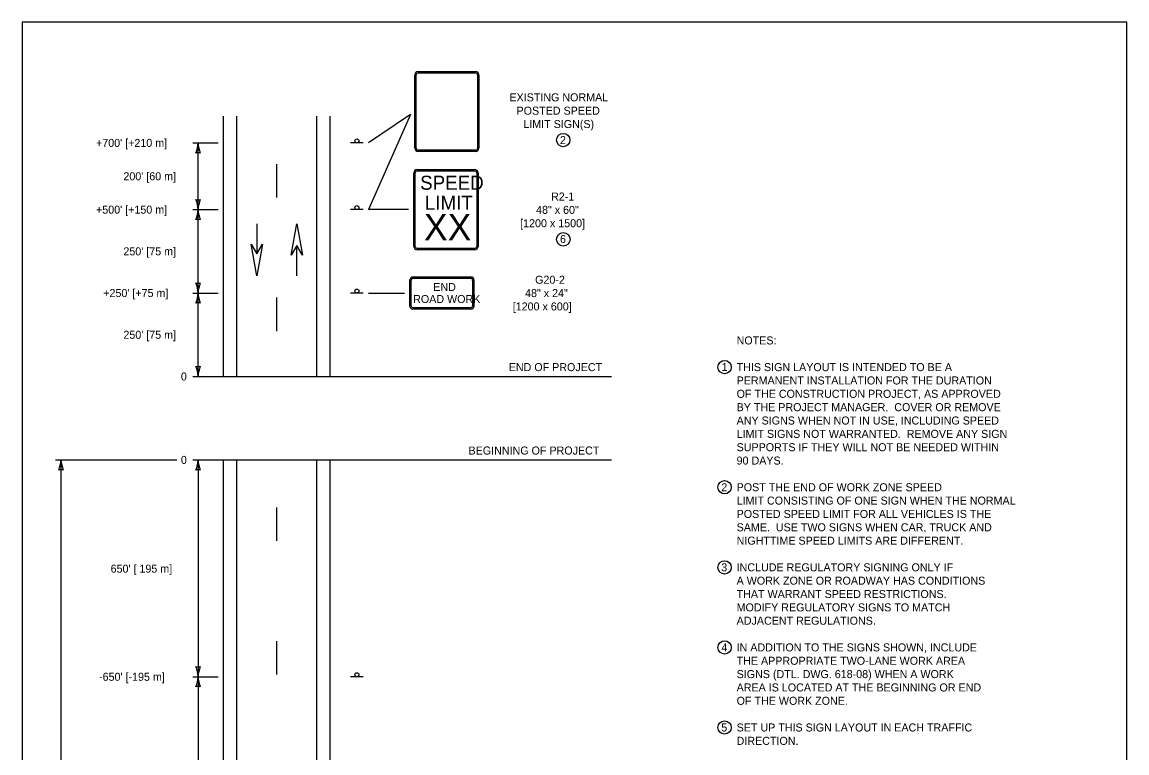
# Model space of a CAD drawing. Extents: x 49991.4 to 50021, y 49987.6 to 50011.4.
# Drawn here: x 50000.34 to 50008.61, y 50005.79 to 50011.26 of the extents above; entities that cross this region are included whole.
import ezdxf

# ---------------------------------------------------------------- set-up
doc = ezdxf.new("R2010")
doc.units = 0
for name, color, linetype in [('Level 1', 7, 'Continuous'), ('Level 2', 7, 'Continuous'), ('Level 3', 7, 'Continuous')]:
    doc.layers.add(name, color=color, linetype=linetype)

msp = doc.modelspace()

# ---------------------------------------------------------------- linework, layer by layer
at = {"layer": 'Level 1'}
for p, q in [((50003.3039, 50010.8925), (50003.7339, 50010.8925)), ((50003.3039, 50010.8825), (50003.7339, 50010.8825)), ((50003.2789, 50010.3175), (50003.2789, 50010.8675)), ((50003.2889, 50010.3175), (50003.2889, 50010.8675)), ((50003.7489, 50010.8675), (50003.7489, 50010.3175)), ((50003.7589, 50010.8675), (50003.7589, 50010.3175)), ((50001.8443, 50008.6077), (50001.8443, 50010.5577)), ((50001.8443, 50008.6077), (50001.8443, 50010.5577)), ((50001.9443, 50008.6077), (50001.9443, 50010.5577)), ((50001.9443, 50008.6077), (50001.9443, 50010.5577)), ((50002.5443, 50008.6077), (50002.5443, 50010.5577)), ((50002.5443, 50008.6077), (50002.5443, 50010.5577)), ((50002.6443, 50008.6077), (50002.6443, 50010.5577)), ((50002.6443, 50008.6077), (50002.6443, 50010.5577)), ((50002.8923, 50010.3577), (50002.7963, 50010.3577)), ((50002.8923, 50010.3577), (50002.7963, 50010.3577)), ((50003.7339, 50010.3025), (50003.3039, 50010.3025)), ((50003.7339, 50010.2925), (50003.3039, 50010.2925)), ((50002.2443, 50009.9482), (50002.2443, 50010.1982)), ((50002.2443, 50009.9482), (50002.2443, 50010.1982)), ((50003.272, 50009.5825), (50003.272, 50010.1325)), ((50003.282, 50009.5825), (50003.282, 50010.1325)), ((50003.297, 50010.1575), (50003.727, 50010.1575)), ((50003.297, 50010.1475), (50003.727, 50010.1475)), ((50003.742, 50010.1325), (50003.742, 50009.5825)), ((50003.752, 50010.1325), (50003.752, 50009.5825)), ((50002.8923, 50009.8575), (50002.7963, 50009.8575)), ((50002.8923, 50009.8575), (50002.7963, 50009.8575)), ((50002.094, 50009.7524), (50002.094, 50009.5265)), ((50002.094, 50009.7524), (50002.094, 50009.5265)), ((50002.0943, 50009.7524), (50002.0943, 50009.5265)), ((50002.0943, 50009.7524), (50002.0943, 50009.5265)), ((50002.394, 50009.3623), (50002.394, 50009.5882)), ((50002.394, 50009.3623), (50002.394, 50009.5882)), ((50002.3943, 50009.3623), (50002.3943, 50009.5882)), ((50002.3943, 50009.3623), (50002.3943, 50009.5882)), ((50003.727, 50009.5675), (50003.297, 50009.5675)), ((50003.727, 50009.5575), (50003.297, 50009.5575)), ((50003.2419, 50009.1325), (50003.2419, 50009.3325)), ((50003.2519, 50009.1375), (50003.2519, 50009.3275)), ((50003.7019, 50009.3525), (50003.2619, 50009.3525)), ((50003.6969, 50009.3425), (50003.2669, 50009.3425)), ((50003.7119, 50009.3275), (50003.7119, 50009.1375)), ((50003.7219, 50009.3325), (50003.7219, 50009.1325)), ((50002.8923, 50009.2325), (50002.7963, 50009.2325)), ((50002.8923, 50009.2325), (50002.7963, 50009.2325)), ((50002.2443, 50008.9482), (50002.2443, 50009.1982)), ((50002.2443, 50008.9482), (50002.2443, 50009.1982)), ((50003.7018, 50009.1125), (50003.2618, 50009.1125)), ((50003.6969, 50009.1225), (50003.2669, 50009.1225)), ((50001.8443, 50002.7972), (50001.8443, 50007.9828)), ((50001.8443, 50002.7972), (50001.8443, 50007.9828)), ((50001.9443, 50002.7972), (50001.9443, 50007.9828)), ((50001.9443, 50002.7972), (50001.9443, 50007.9828)), ((50002.5443, 50002.7972), (50002.5443, 50007.9828)), ((50002.5443, 50002.7972), (50002.5443, 50007.9828)), ((50002.6443, 50002.7972), (50002.6443, 50007.9828)), ((50002.6443, 50002.7972), (50002.6443, 50007.9828)), ((50002.2443, 50007.3756), (50002.2443, 50007.6256)), ((50002.2443, 50007.3756), (50002.2443, 50007.6256)), ((50002.2443, 50006.3756), (50002.2443, 50006.6256)), ((50002.2443, 50006.3756), (50002.2443, 50006.6256)), ((50002.8923, 50006.3575), (50002.7963, 50006.3575)), ((50002.8923, 50006.3575), (50002.7963, 50006.3575))]:
    msp.add_line(p, q, dxfattribs=at)
for points in [[(50008.6146, 50011.2628), (50000.3356, 50011.2628), (50000.3356, 50000.0624), (50008.6146, 50000.0624)], [(50002.3523, 50009.5159), (50002.394, 50009.7524), (50002.4359, 50009.5159), (50002.394, 50009.5881)], [(50002.3523, 50009.5159), (50002.394, 50009.7524), (50002.4359, 50009.5159), (50002.394, 50009.5881)], [(50002.136, 50009.5988), (50002.0943, 50009.3623), (50002.0524, 50009.5988), (50002.0943, 50009.5266)], [(50002.136, 50009.5988), (50002.0943, 50009.3623), (50002.0524, 50009.5988), (50002.0943, 50009.5266)]]:
    msp.add_lwpolyline(points, close=True, dxfattribs=at)
for centre in [(50002.8443, 50010.3728), (50002.8443, 50010.3728), (50002.8443, 50009.8728), (50002.8443, 50009.8728), (50002.8443, 50009.2478), (50002.8443, 50009.2478), (50002.8443, 50006.3728), (50002.8443, 50006.3728)]:
    msp.add_circle(centre, 0.0152, dxfattribs=at)
for centre, radius, start, end in [((50003.3039, 50010.8676), 0.025, 90, 180), ((50003.3039, 50010.8676), 0.015, 90, 180), ((50003.7339, 50010.8676), 0.025, 0, 90), ((50003.7339, 50010.8676), 0.015, 0, 90), ((50003.3039, 50010.3176), 0.025, 180, 270), ((50003.3039, 50010.3176), 0.015, 180, 270), ((50003.7339, 50010.3176), 0.025, 270, 0), ((50003.7339, 50010.3176), 0.015, 270, 0), ((50003.297, 50010.1326), 0.025, 90, 180), ((50003.297, 50010.1326), 0.015, 90, 180), ((50003.727, 50010.1326), 0.025, 0, 90), ((50003.727, 50010.1326), 0.015, 0, 90), ((50003.297, 50009.5826), 0.025, 180, 270), ((50003.297, 50009.5826), 0.015, 180, 270), ((50003.727, 50009.5826), 0.025, 270, 0), ((50003.727, 50009.5826), 0.015, 270, 0), ((50003.2619, 50009.3325), 0.02, 90, 180), ((50003.2669, 50009.3275), 0.015, 90, 180), ((50003.6969, 50009.3275), 0.015, 360, 90), ((50003.7019, 50009.3325), 0.02, 360, 90), ((50003.2669, 50009.1375), 0.015, 180, 270), ((50003.6969, 50009.1375), 0.015, 270, 360), ((50003.2618, 50009.1325), 0.02, 180, 270), ((50003.7018, 50009.1325), 0.02, 270, 360)]:
    msp.add_arc(centre, radius, start, end, dxfattribs=at)
at = {"layer": 'Level 2'}
for centre, radius in [((50004.391, 50010.3791), 0.05), ((50004.3908, 50009.6352), 0.0507), ((50005.6, 50008.6777), 0.05), ((50005.6, 50007.7776), 0.05), ((50005.6, 50007.7776), 0.05), ((50005.6, 50007.1776), 0.05), ((50005.6, 50007.1776), 0.05), ((50005.6, 50006.5777), 0.05), ((50005.5998, 50005.9777), 0.05)]:
    msp.add_circle(centre, radius, dxfattribs=at)
at = {"layer": 'Level 3'}
for p, q in [((50003.2458, 50010.5701), (50002.9323, 50010.3577)), ((50003.2458, 50010.5701), (50002.9323, 50009.8575)), ((50001.6143, 50010.3577), (50001.8043, 50010.3577)), ((50001.6543, 50009.8578), (50001.6543, 50010.3577)), ((50001.6143, 50009.8577), (50001.8043, 50009.8577)), ((50001.6543, 50009.2327), (50001.6543, 50009.8577)), ((50003.232, 50009.8575), (50002.9323, 50009.8575)), ((50001.6143, 50009.2327), (50001.8043, 50009.2327)), ((50001.6543, 50008.6077), (50001.6543, 50009.2327)), ((50002.9323, 50009.2325), (50003.2019, 50009.2325)), ((50001.6143, 50008.6077), (50004.7528, 50008.6077)), ((50000.587, 50007.9828), (50001.4944, 50007.9828)), ((50000.627, 50007.9828), (50000.627, 50002.0173)), ((50001.6143, 50007.9827), (50002.7563, 50007.9827)), ((50001.6543, 50007.9827), (50001.6543, 50006.7896)), ((50002.7563, 50007.9828), (50004.7528, 50007.9828)), ((50002.7563, 50007.9828), (50004.7528, 50007.9828)), ((50001.6543, 50006.7896), (50001.6543, 50006.3577)), ((50001.6143, 50006.3577), (50001.8043, 50006.3577)), ((50001.6543, 50006.3577), (50001.6543, 50004.8576))]:
    msp.add_line(p, q, dxfattribs=at)
for centre, radius, start, end in [((50001.4322, 50010.3669), 0.2223, 337.45601, 357.63952), ((50001.887, 50010.3692), 0.233, 182.82731, 202.07716), ((50001.6543, 50010.2295), 0.0548, 72.13882, 107.86118), ((50001.6543, 50009.986), 0.0548, 252.13882, 287.86118), ((50001.4216, 50009.8463), 0.233, 2.82731, 22.07716), ((50001.8764, 50009.8486), 0.2223, 157.45601, 177.63952), ((50001.4322, 50009.8669), 0.2223, 337.45601, 357.63952), ((50001.887, 50009.8692), 0.233, 182.82731, 202.07716), ((50001.6543, 50009.7295), 0.0548, 72.13882, 107.86118), ((50001.6543, 50009.3609), 0.0548, 252.13882, 287.86118), ((50001.4216, 50009.2212), 0.233, 2.82731, 22.07716), ((50001.8764, 50009.2236), 0.2223, 157.45601, 177.63952), ((50001.4322, 50009.2419), 0.2223, 337.45601, 357.63952), ((50001.887, 50009.2442), 0.233, 182.82731, 202.07716), ((50001.6543, 50009.1045), 0.0548, 72.13882, 107.86118), ((50001.6543, 50008.7359), 0.0548, 252.13882, 287.86118), ((50001.4216, 50008.5962), 0.233, 2.82731, 22.07716), ((50001.8764, 50008.5986), 0.2223, 157.45601, 177.63952), ((50000.4049, 50007.9919), 0.2223, 337.45601, 357.63952), ((50000.8597, 50007.9942), 0.233, 182.82731, 202.07716), ((50001.4322, 50007.9919), 0.2223, 337.45601, 357.63952), ((50001.887, 50007.9942), 0.233, 182.82731, 202.07716), ((50000.627, 50007.8545), 0.0548, 72.13882, 107.86118), ((50001.6543, 50007.8545), 0.0548, 72.13882, 107.86118), ((50001.6543, 50006.4859), 0.0548, 252.13882, 287.86118), ((50001.4216, 50006.3462), 0.233, 2.82731, 22.07716), ((50001.8764, 50006.3486), 0.2223, 157.45601, 177.63952), ((50001.4322, 50006.3669), 0.2223, 337.45601, 357.63952), ((50001.887, 50006.3692), 0.233, 182.82731, 202.07716), ((50001.6543, 50006.2295), 0.0548, 72.13882, 107.86118)]:
    msp.add_arc(centre, radius, start, end, dxfattribs=at)

# ---------------------------------------------------------------- texts
at = {"layer": 'Level 1'}
for s, height, p in [('SPEED', 0.10512, (50003.3183, 50010.0067)), ('LIMIT', 0.10512, (50003.3537, 50009.8566)), ('XX', 0.19892, (50003.3471, 50009.6271))]:
    msp.add_text(s, height=height, dxfattribs=at).set_placement(p)
for s, p in [('END', (50003.4167, 50009.2479)), ('ROAD WORK', (50003.266, 50009.1579))]:
    msp.add_text(s, height=0.06, rotation=360, dxfattribs=at).set_placement(p)
at = {"layer": 'Level 2'}
for s, p in [('EXISTING NORMAL', (50003.9873, 50010.6691)), ('POSTED SPEED', (50004.0408, 50010.5691)), ('LIMIT SIGN(S)', (50004.0916, 50010.4691)), ("+700' [+210 m]", (50000.8897, 50010.3277)), ('2', (50004.3659, 50010.3491)), ("200' [60 m]", (50001.0948, 50010.0777)), ('R2-1', (50004.2994, 50009.9259)), ("+500' [+150 m]", (50000.8897, 50009.8277)), ('48" x 60"', (50004.1871, 50009.8259)), ('[1200 x 1500]', (50004.0677, 50009.7259)), ('6', (50004.3663, 50009.6073)), ("250' [75 m]", (50001.0948, 50009.5152)), ('G20-2', (50004.18, 50009.3025)), ("+250' [+75 m]", (50000.9436, 50009.2027)), ('48" x 24"', (50004.1048, 50009.2025)), ('[1200 x 600]', (50004.0123, 50009.1025)), ("250' [75 m]", (50001.0948, 50008.8902)), ('NOTES:', (50005.69, 50008.8477)), ('0', (50001.5257, 50008.5777)), ('END OF PROJECT', (50003.9823, 50008.6477)), ('1', (50005.5773, 50008.649)), ('THIS SIGN LAYOUT IS INTENDED TO BE A', (50005.69, 50008.6477)), ('PERMANENT INSTALLATION FOR THE DURATION', (50005.69, 50008.5477)), ('OF THE CONSTRUCTION PROJECT, AS APPROVED', (50005.69, 50008.4477)), ('BY THE PROJECT MANAGER.  COVER OR REMOVE', (50005.69, 50008.3477)), ('ANY SIGNS WHEN NOT IN USE, INCLUDING SPEED', (50005.69, 50008.2477)), ('LIMIT SIGNS NOT WARRANTED.  REMOVE ANY SIGN', (50005.69, 50008.1477)), ('BEGINNING OF PROJECT', (50003.681, 50008.0228)), ('SUPPORTS IF THEY WILL NOT BE NEEDED WITHIN', (50005.69, 50008.0477)), ('0', (50001.5257, 50007.9527)), ('90 DAYS.', (50005.69, 50007.9477)), ('2', (50005.575, 50007.7477)), ('2', (50005.575, 50007.7477)), ('POST THE END OF WORK ZONE SPEED', (50005.69, 50007.7477)), ('LIMIT CONSISTING OF ONE SIGN WHEN THE NORMAL', (50005.69, 50007.6477)), ('POSTED SPEED LIMIT FOR ALL VEHICLES IS THE', (50005.69, 50007.5477)), ('SAME.  USE TWO SIGNS WHEN CAR, TRUCK AND ', (50005.69, 50007.4477)), ('NIGHTTIME SPEED LIMITS ARE DIFFERENT.', (50005.69, 50007.3477)), ("650' [ 195 m]", (50000.9989, 50007.1377)), ('3', (50005.5749, 50007.1478)), ('3', (50005.5749, 50007.1478)), ('INCLUDE REGULATORY SIGNING ONLY IF ', (50005.69, 50007.1477)), ('A WORK ZONE OR ROADWAY HAS CONDITIONS', (50005.69, 50007.0477)), ('THAT WARRANT SPEED RESTRICTIONS. ', (50005.69, 50006.9477)), ('MODIFY REGULATORY SIGNS TO MATCH', (50005.69, 50006.8477)), ('ADJACENT REGULATIONS.', (50005.69, 50006.7477)), ('4', (50005.5761, 50006.5478)), ('4', (50005.5761, 50006.5478)), ('IN ADDITION TO THE SIGNS SHOWN, INCLUDE', (50005.69, 50006.5477)), ('THE APPROPRIATE TWO-LANE WORK AREA', (50005.69, 50006.4477)), ('SIGNS (DTL. DWG. 618-08) WHEN A WORK ', (50005.69, 50006.3477)), ("-650' [-195 m]", (50000.9124, 50006.3277)), ('AREA IS LOCATED AT THE BEGINNING OR END ', (50005.69, 50006.2477)), ('OF THE WORK ZONE.', (50005.69, 50006.1477)), ('5', (50005.575, 50005.9477)), ('SET UP THIS SIGN LAYOUT IN EACH TRAFFIC', (50005.69, 50005.9477)), ('DIRECTION.', (50005.69, 50005.8477))]:
    msp.add_text(s, height=0.06, dxfattribs=at).set_placement(p)

doc.saveas('drawing.dxf')
